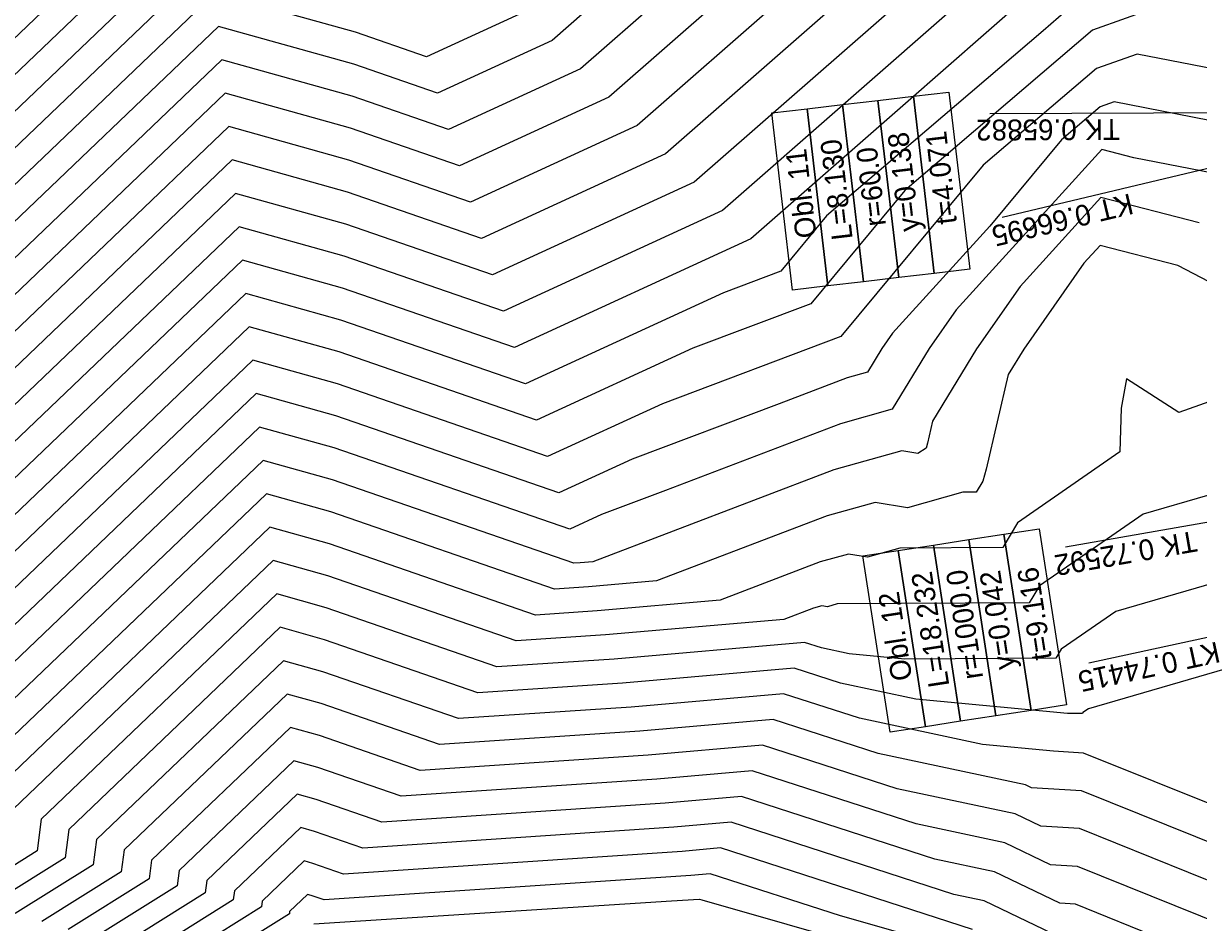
# Model space of a CAD drawing. Extents: x -549394 to -546608, y -1037055 to -1033629.
# Drawn here: x -547411.6 to -547213.9, y -1036262.8 to -1036111.6 of the extents above; entities that cross this region are included whole.
import ezdxf

# ---------------------------------------------------------------- set-up
doc = ezdxf.new("R2010")
doc.units = 0
for name, color, linetype in [('hlavni_vrst', 7, 'Continuous'), ('norm_vrst', 7, 'Continuous'), ('x_popis_oblouky_C31', 7, 'Continuous')]:
    doc.layers.add(name, color=color, linetype=linetype)

msp = doc.modelspace()

# ---------------------------------------------------------------- linework, layer by layer
at = {"layer": 'hlavni_vrst'}
for p, q in [((-547381.07, -1036089.63), (-547506.12, -1036209.19)), ((-547285.75, -1036091.08), (-547317.86, -1036119.19)), ((-547240.75, -1036096.43), (-547293.98, -1036143.02)), ((-547378.19, -1036117.71), (-547482.89, -1036217.82)), ((-547356.25, -1036123.83), (-547378.19, -1036117.71)), ((-547317.86, -1036119.19), (-547340.07, -1036129.43)), ((-547340.07, -1036129.43), (-547356.25, -1036123.83)), ((-547230.43, -1036125.6), (-547236.94, -1036131.17)), ((-547228.09, -1036124.77), (-547230.43, -1036125.6)), ((-547207.41, -1036128.8), (-547228.09, -1036124.77)), ((-547236.94, -1036131.17), (-547248.99, -1036145.66)), ((-547293.98, -1036143.02), (-547330.8, -1036160)), ((-547375.3, -1036145.78), (-547459.67, -1036226.45)), ((-547357.63, -1036150.72), (-547375.3, -1036145.78)), ((-547248.99, -1036145.66), (-547265.39, -1036163.7)), ((-547330.8, -1036160), (-547357.63, -1036150.72)), ((-547265.39, -1036163.7), (-547267.17, -1036166.24)), ((-547267.17, -1036166.24), (-547269.59, -1036170.23)), ((-547272.99, -1036171.18), (-547284.47, -1036175.56)), ((-547269.59, -1036170.23), (-547272.99, -1036171.18)), ((-547372.42, -1036173.86), (-547436.45, -1036235.08)), ((-547359.01, -1036177.61), (-547372.42, -1036173.86)), ((-547284.47, -1036175.56), (-547309.19, -1036184.88)), ((-547321.53, -1036190.57), (-547359.01, -1036177.61)), ((-547309.19, -1036184.88), (-547321.53, -1036190.57)), ((-547212.4, -1036190.97), (-547223.21, -1036194.11)), ((-547223.21, -1036194.11), (-547240.67, -1036206.21)), ((-547369.54, -1036201.94), (-547413.23, -1036243.71)), ((-547360.39, -1036204.49), (-547369.54, -1036201.94)), ((-547328.68, -1036215.46), (-547360.39, -1036204.49)), ((-547240.67, -1036206.21), (-547242.36, -1036209.04)), ((-547274.7, -1036209.24), (-547276.32, -1036209.7)), ((-547242.36, -1036209.04), (-547274.7, -1036209.24)), ((-547278.66, -1036209.93), (-547283.64, -1036211.83)), ((-547277.26, -1036209.54), (-547278.66, -1036209.93)), ((-547276.32, -1036209.7), (-547277.26, -1036209.54)), ((-547283.64, -1036211.83), (-547313.63, -1036214.46)), ((-547313.63, -1036214.46), (-547328.68, -1036215.46)), ((-547366.66, -1036230.02), (-547390.01, -1036252.34)), ((-547361.77, -1036231.38), (-547366.66, -1036230.02)), ((-547344.82, -1036237.24), (-547361.77, -1036231.38)), ((-547287.23, -1036233), (-547306.47, -1036234.68)), ((-547264.6, -1036240.32), (-547287.23, -1036233)), ((-547306.47, -1036234.68), (-547344.82, -1036237.24)), ((-547244.76, -1036244.54), (-547264.6, -1036240.32)), ((-547240.4, -1036246.64), (-547244.76, -1036244.54)), ((-547233.92, -1036247.04), (-547240.4, -1036246.64)), ((-547197.57, -1036261.66), (-547233.92, -1036247.04)), ((-547390.01, -1036252.34), (-547390.42, -1036255.49)), ((-547296.06, -1036254.62), (-547299.32, -1036254.9)), ((-547274.12, -1036261.72), (-547296.06, -1036254.62)), ((-547390.42, -1036255.49), (-547404.04, -1036264)), ((-547299.32, -1036254.9), (-547360.96, -1036259.03)), ((-547363.78, -1036258.09), (-547366.79, -1036260.97)), ((-547363.15, -1036258.27), (-547363.78, -1036258.09)), ((-547360.96, -1036259.03), (-547363.15, -1036258.27)), ((-547366.84, -1036261.38), (-547381.81, -1036270.72)), ((-547366.79, -1036260.97), (-547366.84, -1036261.38)), ((-547256.01, -1036266.88), (-547274.12, -1036261.72))]:
    msp.add_line(p, q, dxfattribs=at)
at = {"layer": 'norm_vrst'}
for p, q in [((-547381.64, -1036084.01), (-547510.76, -1036207.47)), ((-547294.76, -1036090.01), (-547322.64, -1036114.42)), ((-547276.75, -1036092.15), (-547313.09, -1036123.96)), ((-547267.75, -1036093.22), (-547308.31, -1036128.72)), ((-547258.75, -1036094.29), (-547303.54, -1036133.49)), ((-547380.49, -1036095.24), (-547501.47, -1036210.92)), ((-547249.75, -1036095.36), (-547298.76, -1036138.26)), ((-547232.29, -1036097.92), (-547263.21, -1036125.03)), ((-547379.92, -1036100.86), (-547496.83, -1036212.64)), ((-547379.34, -1036106.47), (-547492.18, -1036214.37)), ((-547355.7, -1036113.07), (-547379.34, -1036106.47)), ((-547232.29, -1036106.04), (-547240.02, -1036112.82)), ((-547327.42, -1036109.66), (-547343.78, -1036117.2)), ((-547220.38, -1036108.68), (-547231.74, -1036112.73)), ((-547378.76, -1036112.09), (-547487.54, -1036216.1)), ((-547355.98, -1036118.45), (-547378.76, -1036112.09)), ((-547343.78, -1036117.2), (-547355.7, -1036113.07)), ((-547322.64, -1036114.42), (-547341.92, -1036123.31)), ((-547240.02, -1036112.82), (-547276.46, -1036143.97)), ((-547231.74, -1036112.73), (-547263.28, -1036139.71)), ((-547224.23, -1036116.72), (-547231.08, -1036119.17)), ((-547208.17, -1036119.85), (-547224.23, -1036116.72)), ((-547341.92, -1036123.31), (-547355.98, -1036118.45)), ((-547231.08, -1036119.17), (-547250.11, -1036135.44)), ((-547377.61, -1036123.32), (-547478.25, -1036219.55)), ((-547356.53, -1036129.21), (-547377.61, -1036123.32)), ((-547313.09, -1036123.96), (-547338.22, -1036135.54)), ((-547263.21, -1036125.03), (-547289.21, -1036147.79)), ((-547377.03, -1036128.94), (-547473.61, -1036221.27)), ((-547356.81, -1036134.59), (-547377.03, -1036128.94)), ((-547338.22, -1036135.54), (-547356.53, -1036129.21)), ((-547308.31, -1036128.72), (-547336.36, -1036141.66)), ((-547303.54, -1036133.49), (-547334.51, -1036147.77)), ((-547230.16, -1036132.81), (-547254.65, -1036159.77)), ((-547224.8, -1036134.2), (-547230.16, -1036132.81)), ((-547206.65, -1036137.74), (-547224.8, -1036134.2)), ((-547376.46, -1036134.55), (-547468.96, -1036223)), ((-547357.08, -1036139.96), (-547376.46, -1036134.55)), ((-547336.36, -1036141.66), (-547356.81, -1036134.59)), ((-547250.11, -1036135.44), (-547274.08, -1036164.24)), ((-547334.51, -1036147.77), (-547357.08, -1036139.96)), ((-547298.76, -1036138.26), (-547332.65, -1036153.88)), ((-547263.28, -1036139.71), (-547279.13, -1036158.75)), ((-547375.88, -1036140.17), (-547464.32, -1036224.73)), ((-547357.36, -1036145.34), (-547375.88, -1036140.17)), ((-547230.31, -1036140.87), (-547243.91, -1036155.84)), ((-547213.78, -1036145.14), (-547230.31, -1036140.87)), ((-547276.46, -1036143.97), (-547284.17, -1036153.25)), ((-547332.65, -1036153.88), (-547357.36, -1036145.34)), ((-547289.21, -1036147.79), (-547328.95, -1036166.11)), ((-547230.45, -1036148.92), (-547233.17, -1036151.91)), ((-547217.37, -1036152.31), (-547230.45, -1036148.92)), ((-547374.73, -1036151.4), (-547455.03, -1036228.18)), ((-547357.91, -1036156.1), (-547374.73, -1036151.4)), ((-547233.17, -1036151.91), (-547243.31, -1036166.35)), ((-547284.17, -1036153.25), (-547293.83, -1036156.89)), ((-547212.13, -1036155.02), (-547217.37, -1036152.31)), ((-547243.91, -1036155.84), (-547251.27, -1036166.31)), ((-547374.15, -1036157.01), (-547450.38, -1036229.9)), ((-547358.18, -1036161.47), (-547374.15, -1036157.01)), ((-547328.95, -1036166.11), (-547357.91, -1036156.1)), ((-547293.83, -1036156.89), (-547327.09, -1036172.23)), ((-547279.13, -1036158.75), (-547298.95, -1036166.22)), ((-547254.65, -1036159.77), (-547259.22, -1036166.28)), ((-547327.09, -1036172.23), (-547358.18, -1036161.47)), ((-547373.58, -1036162.63), (-547445.74, -1036231.63)), ((-547358.46, -1036166.85), (-547373.58, -1036162.63)), ((-547274.08, -1036164.24), (-547304.07, -1036175.55)), ((-547325.24, -1036178.34), (-547358.46, -1036166.85)), ((-547298.95, -1036166.22), (-547325.24, -1036178.34)), ((-547259.22, -1036166.28), (-547265.41, -1036176.49)), ((-547251.27, -1036166.31), (-547258.66, -1036178.51)), ((-547243.31, -1036166.35), (-547245.91, -1036170.63)), ((-547373, -1036168.25), (-547441.1, -1036233.36)), ((-547358.74, -1036172.23), (-547373, -1036168.25)), ((-547245.91, -1036170.63), (-547249.62, -1036186.56)), ((-547226.03, -1036171.38), (-547226.93, -1036176.31)), ((-547217.22, -1036177.01), (-547226.03, -1036171.38)), ((-547201.57, -1036171.51), (-547217.22, -1036177.01)), ((-547323.39, -1036184.45), (-547358.74, -1036172.23)), ((-547304.07, -1036175.55), (-547323.39, -1036184.45)), ((-547265.41, -1036176.49), (-547274.12, -1036178.93)), ((-547226.93, -1036176.31), (-547227.11, -1036183.63)), ((-547371.85, -1036179.48), (-547431.81, -1036236.81)), ((-547359.29, -1036182.98), (-547371.85, -1036179.48)), ((-547274.12, -1036178.93), (-547303.56, -1036190.15)), ((-547258.66, -1036178.51), (-547259.51, -1036182.19)), ((-547319.68, -1036196.68), (-547359.29, -1036182.98)), ((-547263.82, -1036183.49), (-547275.26, -1036186.68)), ((-547261.11, -1036183.93), (-547263.82, -1036183.49)), ((-547259.74, -1036183.01), (-547261.11, -1036183.93)), ((-547259.51, -1036182.19), (-547259.74, -1036183.01)), ((-547371.27, -1036185.09), (-547427.16, -1036238.53)), ((-547359.56, -1036188.36), (-547371.27, -1036185.09)), ((-547227.11, -1036183.63), (-547244.34, -1036195.57)), ((-547275.26, -1036186.68), (-547315.79, -1036202.13)), ((-547249.62, -1036186.56), (-547250.16, -1036188.56)), ((-547318.99, -1036202.39), (-547359.56, -1036188.36)), ((-547250.16, -1036188.56), (-547251.29, -1036190.44)), ((-547370.69, -1036190.71), (-547422.52, -1036240.26)), ((-547359.84, -1036193.74), (-547370.69, -1036190.71)), ((-547303.56, -1036190.15), (-547314.31, -1036194.21)), ((-547253.55, -1036190.46), (-547262.87, -1036193.07)), ((-547251.29, -1036190.44), (-547253.55, -1036190.46)), ((-547268.3, -1036192.17), (-547276.39, -1036194.43)), ((-547262.87, -1036193.07), (-547268.3, -1036192.17)), ((-547322.22, -1036206.75), (-547359.84, -1036193.74)), ((-547314.31, -1036194.21), (-547319.68, -1036196.68)), ((-547276.39, -1036194.43), (-547305.07, -1036205.37)), ((-547370.12, -1036196.32), (-547417.87, -1036241.99)), ((-547360.11, -1036199.12), (-547370.12, -1036196.32)), ((-547244.34, -1036195.57), (-547246.83, -1036199.74)), ((-547325.45, -1036211.1), (-547360.11, -1036199.12)), ((-547272.78, -1036200.86), (-547277.53, -1036202.18)), ((-547269.6, -1036201.38), (-547272.78, -1036200.86)), ((-547264.12, -1036199.85), (-547269.6, -1036201.38)), ((-547246.83, -1036199.74), (-547264.12, -1036199.85)), ((-547317.92, -1036202.32), (-547318.99, -1036202.39)), ((-547315.79, -1036202.13), (-547317.92, -1036202.32)), ((-547277.53, -1036202.18), (-547294.36, -1036208.6)), ((-547202.22, -1036203.05), (-547227.82, -1036210.48)), ((-547316.49, -1036206.37), (-547322.22, -1036206.75)), ((-547305.07, -1036205.37), (-547316.49, -1036206.37)), ((-547368.96, -1036207.55), (-547408.59, -1036245.44)), ((-547360.67, -1036209.87), (-547368.96, -1036207.55)), ((-547294.36, -1036208.6), (-547315.06, -1036210.41)), ((-547331.91, -1036219.82), (-547360.67, -1036209.87)), ((-547315.06, -1036210.41), (-547325.45, -1036211.1)), ((-547227.82, -1036210.48), (-547237.01, -1036216.85)), ((-547368.39, -1036213.17), (-547403.94, -1036247.16)), ((-547360.94, -1036215.25), (-547368.39, -1036213.17)), ((-547335.13, -1036224.17), (-547360.94, -1036215.25)), ((-547280.16, -1036215.7), (-547312.2, -1036218.5)), ((-547277.3, -1036216.63), (-547280.16, -1036215.7)), ((-547272.64, -1036217.62), (-547277.3, -1036216.63)), ((-547237.01, -1036216.85), (-547237.9, -1036218.34)), ((-547367.81, -1036218.79), (-547399.3, -1036248.89)), ((-547361.22, -1036220.63), (-547367.81, -1036218.79)), ((-547312.2, -1036218.5), (-547331.91, -1036219.82)), ((-547263.28, -1036218.5), (-547272.64, -1036217.62)), ((-547237.9, -1036218.34), (-547263.28, -1036218.5)), ((-547338.36, -1036228.53), (-547361.22, -1036220.63)), ((-547281.93, -1036220.02), (-547310.77, -1036222.54)), ((-547274.12, -1036222.55), (-547281.93, -1036220.02)), ((-547206.86, -1036219.43), (-547232.43, -1036226.86)), ((-547310.77, -1036222.54), (-547335.13, -1036224.17)), ((-547261.43, -1036225.25), (-547274.12, -1036222.55)), ((-547367.23, -1036224.4), (-547394.65, -1036250.62)), ((-547361.49, -1036226), (-547367.23, -1036224.4)), ((-547283.7, -1036224.35), (-547309.34, -1036226.59)), ((-547270.95, -1036228.47), (-547283.7, -1036224.35)), ((-547341.59, -1036232.89), (-547361.49, -1036226)), ((-547309.34, -1036226.59), (-547338.36, -1036228.53)), ((-547235.95, -1036227.65), (-547261.43, -1036225.25)), ((-547232.43, -1036226.86), (-547233.34, -1036227.49)), ((-547285.46, -1036228.67), (-547307.9, -1036230.63)), ((-547267.77, -1036234.4), (-547285.46, -1036228.67)), ((-547250.22, -1036232.88), (-547270.95, -1036228.47)), ((-547233.43, -1036227.64), (-547235.95, -1036227.65)), ((-547233.34, -1036227.49), (-547233.43, -1036227.64)), ((-547307.9, -1036230.63), (-547341.59, -1036232.89)), ((-547238.32, -1036234.01), (-547250.22, -1036232.88)), ((-547243.03, -1036239.66), (-547267.77, -1036234.4)), ((-547233.24, -1036234.32), (-547238.32, -1036234.01)), ((-547199.85, -1036247.75), (-547233.24, -1036234.32)), ((-547366.08, -1036235.63), (-547385.36, -1036254.07)), ((-547362.04, -1036236.76), (-547366.08, -1036235.63)), ((-547348.05, -1036241.6), (-547362.04, -1036236.76)), ((-547305.04, -1036238.72), (-547348.05, -1036241.6)), ((-547288.99, -1036237.32), (-547305.04, -1036238.72)), ((-547261.42, -1036246.24), (-547288.99, -1036237.32)), ((-547242, -1036240.16), (-547243.03, -1036239.66)), ((-547233.58, -1036240.68), (-547242, -1036240.16)), ((-547186.37, -1036259.67), (-547233.58, -1036240.68)), ((-547365.51, -1036241.25), (-547380.72, -1036255.79)), ((-547362.32, -1036242.14), (-547365.51, -1036241.25)), ((-547351.28, -1036245.96), (-547362.32, -1036242.14)), ((-547303.61, -1036242.77), (-547351.28, -1036245.96)), ((-547290.76, -1036241.65), (-547303.61, -1036242.77)), ((-547258.25, -1036252.17), (-547290.76, -1036241.65)), ((-547408.59, -1036245.44), (-547409.28, -1036250.78)), ((-547364.93, -1036246.86), (-547376.08, -1036257.52)), ((-547362.59, -1036247.52), (-547364.93, -1036246.86)), ((-547302.18, -1036246.81), (-547354.5, -1036250.31)), ((-547292.53, -1036245.97), (-547302.18, -1036246.81)), ((-547255.07, -1036258.09), (-547292.53, -1036245.97)), ((-547246.5, -1036249.42), (-547261.42, -1036246.24)), ((-547403.94, -1036247.16), (-547404.56, -1036251.96)), ((-547354.5, -1036250.31), (-547362.59, -1036247.52)), ((-547409.28, -1036250.78), (-547421.83, -1036258.62)), ((-547399.3, -1036248.89), (-547399.85, -1036253.14)), ((-547394.65, -1036250.62), (-547395.13, -1036254.32)), ((-547294.29, -1036250.29), (-547300.75, -1036250.86)), ((-547251.9, -1036264.01), (-547294.29, -1036250.29)), ((-547238.81, -1036253.12), (-547246.5, -1036249.42)), ((-547404.56, -1036251.96), (-547417.38, -1036259.96)), ((-547364.35, -1036252.48), (-547371.43, -1036259.25)), ((-547362.87, -1036252.89), (-547364.35, -1036252.48)), ((-547300.75, -1036250.86), (-547357.73, -1036254.67)), ((-547248.23, -1036254.3), (-547258.25, -1036252.17)), ((-547399.85, -1036253.14), (-547412.94, -1036261.31)), ((-547395.13, -1036254.32), (-547408.49, -1036262.65)), ((-547385.36, -1036254.07), (-547385.7, -1036256.67)), ((-547357.73, -1036254.67), (-547362.87, -1036252.89)), ((-547237.21, -1036259.6), (-547248.23, -1036254.3)), ((-547234.26, -1036253.4), (-547238.81, -1036253.12)), ((-547208.76, -1036263.66), (-547234.26, -1036253.4)), ((-547385.7, -1036256.67), (-547399.6, -1036265.34)), ((-547380.72, -1036255.79), (-547380.99, -1036257.85)), ((-547380.99, -1036257.85), (-547395.15, -1036266.69)), ((-547376.08, -1036257.52), (-547376.27, -1036259.02)), ((-547249.97, -1036259.18), (-547255.07, -1036258.09)), ((-547376.27, -1036259.02), (-547390.71, -1036268.03)), ((-547371.55, -1036260.2), (-547386.26, -1036269.38)), ((-547371.43, -1036259.25), (-547371.55, -1036260.2)), ((-547302.54, -1036259.26), (-547362.75, -1036263.13)), ((-547297.89, -1036258.95), (-547302.54, -1036259.26)), ((-547297.82, -1036258.94), (-547297.89, -1036258.95)), ((-547297.39, -1036259.08), (-547297.82, -1036258.94)), ((-547260.43, -1036269.62), (-547297.39, -1036259.08)), ((-547235.62, -1036266.08), (-547249.97, -1036259.18)), ((-547234.6, -1036259.76), (-547237.21, -1036259.6)), ((-547219.95, -1036265.66), (-547234.6, -1036259.76))]:
    msp.add_line(p, q, dxfattribs=at)
at = {"layer": 'x_popis_oblouky_C31'}
for points in [[(-547264.31, -1036154.32), (-547267.82, -1036124.53), (-547261.86, -1036123.83), (-547258.35, -1036153.62)], [(-547258.35, -1036153.62), (-547261.86, -1036123.83), (-547255.9, -1036123.12), (-547252.39, -1036152.92)], [(-547282.19, -1036156.43), (-547285.7, -1036126.63), (-547279.74, -1036125.93), (-547276.23, -1036155.73)], [(-547276.23, -1036155.73), (-547279.74, -1036125.93), (-547273.78, -1036125.23), (-547270.27, -1036155.02)], [(-547270.27, -1036155.02), (-547273.78, -1036125.23), (-547267.82, -1036124.53), (-547264.31, -1036154.32)], [(-547242.06, -1036227.15), (-547246.63, -1036197.5), (-547240.7, -1036196.59), (-547236.13, -1036226.23)], [(-547259.85, -1036229.89), (-547264.42, -1036200.25), (-547258.49, -1036199.33), (-547253.92, -1036228.98)], [(-547253.92, -1036228.98), (-547258.49, -1036199.33), (-547252.56, -1036198.42), (-547247.99, -1036228.06)], [(-547247.99, -1036228.06), (-547252.56, -1036198.42), (-547246.63, -1036197.5), (-547242.06, -1036227.15)], [(-547265.78, -1036230.81), (-547270.35, -1036201.16), (-547264.42, -1036200.25), (-547259.85, -1036229.89)]]:
    msp.add_lwpolyline(points, close=True, dxfattribs=at)
for points in [[(-547207.66, -1036126.59), (-547249.03, -1036126.77)], [(-547206.67, -1036134.66), (-547246.92, -1036144.24)], [(-547195.53, -1036192.57), (-547236.28, -1036199.71)], [(-547191.93, -1036210.44), (-547232.36, -1036219.21)]]:
    msp.add_lwpolyline(points, dxfattribs=at)

# ---------------------------------------------------------------- texts
for s, rotation, p in [('TK 0.65882', 180.2359, (-547227.11, -1036127.67)), ('y=0.138', 96.7404, (-547260.78, -1036146.37)), ('t=4.071', 96.7404, (-547254.52, -1036145.16)), ('L=8.130', 96.7404, (-547272.07, -1036147.81)), ('Obl. 11', 96.7404, (-547278.15, -1036147.49)), ('r=60.0', 96.7404, (-547266.47, -1036145.51)), ('KT 0.66695', 193.3925, (-547225.4, -1036140.14)), ('TK 0.72592', 189.9439, (-547214.52, -1036196.91)), ('t=9.116', 98.7936, (-547238.56, -1036218.4)), ('L=18.232', 98.7936, (-547255.8, -1036222.99)), ('r=1000.0', 98.7936, (-547250.11, -1036221.64)), ('y=0.042', 98.7936, (-547244.74, -1036219.99)), ('Obl. 12', 98.7936, (-547262.04, -1036221.89)), ('KT 0.74415', 192.2433, (-547210.76, -1036215.55))]:
    msp.add_text(s, height=3.5, rotation=rotation, dxfattribs=at).set_placement(p)

doc.saveas('drawing.dxf')
